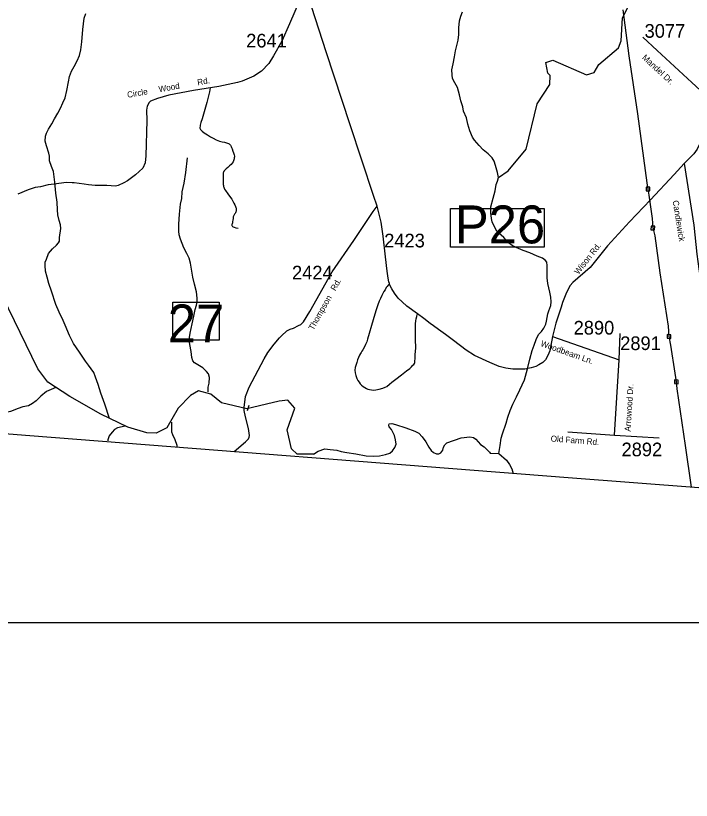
# Model space of a CAD drawing. Extents: x 1268485 to 1426702, y 514839 to 616766.
# Drawn here: x 1345954 to 1353261, y 515585 to 524068 of the extents above; entities that cross this region are included whole.
import ezdxf

# ---------------------------------------------------------------- set-up
doc = ezdxf.new("R2010")
doc.units = 0
for name, color, linetype in [('Old_Level_11', 7, 'Continuous'), ('Old_Level_31', 7, 'Continuous'), ('Old_Level_32', 7, 'Continuous'), ('Old_Level_35', 7, 'Continuous'), ('Old_Level_50', 7, 'Continuous'), ('Old_Level_52', 7, 'Continuous'), ('Old_Level_56', 7, 'Continuous'), ('Old_Level_59', 7, 'Continuous'), ('Old_Level_62', 7, 'Continuous'), ('Old_Level_63', 7, 'Continuous'), ('Old_Level_8', 7, 'Continuous')]:
    doc.layers.add(name, color=color, linetype=linetype)

msp = doc.modelspace()

# ---------------------------------------------------------------- linework, layer by layer
at = {"layer": 'Old_Level_31'}
for p, q in [((1351484.328, 520249.176), (1351484.328, 520249.176)), ((1348424.398, 519825.479), (1348424.398, 519825.479))]:
    msp.add_line(p, q, dxfattribs=at)
for points in [[(1350656.142, 521982.598), (1351670.986, 521982.598), (1351670.986, 521563.836), (1350656.142, 521563.836), (1350656.142, 521982.598)], [(1347652.648, 520970.323), (1348154.735, 520970.323), (1348154.735, 520560.496), (1347652.648, 520560.496), (1347652.648, 520970.323)]]:
    msp.add_lwpolyline(points, dxfattribs=at)
at = {"layer": 'Old_Level_32'}
for p, q in [((1352481.441, 520346.066), (1352491.89, 520631.785)), ((1351759.284, 520600.135), (1352481.441, 520346.066)), ((1352430.298, 519531.943), (1352481.441, 520346.066)), ((1351926.445, 519570.535), (1352430.298, 519531.943)), ((1352430.298, 519531.943), (1352912.367, 519503.458))]:
    msp.add_line(p, q, dxfattribs=at)
for points in [[(1349862.272, 522009.451), (1349824.73, 522122.46), (1349572.702, 522887.349), (1349310.782, 523676.541), (1349155.206, 524158.101), (1349105.065, 524367.979)], [(1349065.286, 524334.899), (1348915.363, 523981.746), (1348833.108, 523793.006), (1348743.774, 523634.247), (1348691.425, 523551.301), (1348611.448, 523469.811), (1348528.119, 523414.661), (1348405.16, 523361.807), (1348352.123, 523345.267), (1348151.34, 523301.161), (1347877.629, 523257.975), (1347608.654, 523210.193), (1347489.32, 523173.437), (1347411.931, 523143.266), (1347398.844, 523128.714), (1347376.864, 523088.761), (1347370.018, 523046.878), (1347371.363, 522934.797), (1347361.036, 522554.496), (1347355.219, 522478.827), (1347327.591, 522420.619), (1347249.068, 522346.404), (1347163.273, 522282.376), (1347125.466, 522260.548), (1347061.484, 522231.445), (1347032.401, 522225.624), (1346939.337, 522232.9), (1346812.826, 522232.9), (1346740.168, 522240.774), (1346694.707, 522248.126), (1346586.253, 522261.667), (1346564.251, 522262.11), (1346504.341, 522263.747), (1346419.102, 522252.72), (1346369.854, 522245.369), (1346305.451, 522238.018), (1346224.001, 522217.803), (1346163.387, 522210.451), (1346087.619, 522186.56), (1345975.863, 522138.779)], [(1353537.161, 523096.675), (1353266.596, 523346.181), (1352892.233, 523690.602), (1352735.016, 523837.622)], [(1353537.161, 523096.675), (1353500.054, 522977.251), (1353413.978, 522807.132), (1353324.923, 522623.315), (1353287.817, 522575.04), (1353184.651, 522468.203)], [(1353184.651, 522468.203), (1353074.457, 522349.632), (1352818.424, 522077.436), (1352593.932, 521837.917), (1352354.596, 521579.832), (1352166.735, 521344.382), (1351977.972, 521183.613), (1351951.997, 521150.191), (1351911.18, 521074.065), (1351866.653, 520966.375), (1351851.81, 520916.243), (1351796.221, 520744.399), (1351759.284, 520600.135)], [(1353184.651, 522468.203), (1353289.673, 521801.897), (1353321.213, 521489.966), (1353363.462, 521174.024)], [(1348425.689, 519823.896), (1348425.319, 519832.419), (1348438.406, 519950.871), (1348480.576, 520050.698), (1348640.531, 520356.287), (1348679.792, 520426.136), (1348748.91, 520515.931), (1348808.282, 520586.487), (1348828.691, 520606.911), (1348886.104, 520662.242), (1348922.668, 520679.514), (1348958.94, 520690.464), (1349012.746, 520718.315), (1349038.721, 520729.455), (1349047.999, 520740.596), (1349060.986, 520751.736), (1349068.408, 520759.163), (1349136.819, 520870.899), (1349376.031, 521298.729), (1349612.058, 521636.906), (1349821.106, 521952.452), (1349862.272, 522009.451)], [(1351759.284, 520600.135), (1351730.398, 520445.305), (1351710.51, 520393.847), (1351682.097, 520346.985), (1351653.684, 520316.662), (1351612.516, 520294.237), (1351580.975, 520273.813), (1351527.169, 520260.816), (1351460.952, 520245.449), (1351415.845, 520245.962), (1351330.497, 520247.819), (1351255.907, 520256.015), (1351182.034, 520274.393), (1351081.642, 520316.662), (1350915.901, 520395.685), (1350825.927, 520451.736), (1350687.179, 520556.029), (1350601.941, 520620.35), (1350526.173, 520674.564), (1350473.61, 520714.535), (1350437.62, 520740.263), (1350369.43, 520792.639), (1350298.398, 520843.177), (1350185.695, 520926.794), (1350134.553, 520972.738), (1350090.986, 521015.006), (1350049.787, 521068.761), (1350022.321, 521114.705), (1350000.538, 521154.216), (1349996.096, 521171.883), (1349991.067, 521191.89), (1349982.069, 521231.861), (1349970.704, 521304.452), (1349953.657, 521461.58), (1349927.146, 521683.791), (1349908.197, 521835.561), (1349862.272, 522009.451)], [(1348316.159, 519354.427), (1348439.86, 519461.928), (1348470.397, 519493.943), (1348479.516, 519511.362), (1348483.186, 519529.499), (1348470.397, 519604.537), (1348439.525, 519729.578), (1348426.773, 519798.949), (1348425.689, 519823.896)]]:
    msp.add_lwpolyline(points, dxfattribs=at)
at = {"layer": 'Old_Level_35'}
for points in [[(1348058.225, 523288.458), (1348050.023, 523245.192), (1348020.393, 523128.773), (1347992.096, 523026.76), (1347970.361, 522953.095), (1347957.237, 522912.956), (1347949.958, 522885.325), (1347947.395, 522872.817), (1347945.344, 522859.642), (1347946.78, 522853.08), (1347948.625, 522845.186), (1347952.624, 522837.291), (1347958.468, 522828.731), (1347969.745, 522818.888), (1347990.763, 522802.382), (1348030.236, 522778.083), (1348062.532, 522757.014), (1348089.496, 522742.557), (1348121.792, 522726.768), (1348158.496, 522712.261), (1348186.896, 522704.367), (1348212.527, 522699.138), (1348232.827, 522694.524), (1348245.951, 522690.577), (1348254.05, 522687.296), (1348261.842, 522682.682), (1348270.352, 522675.454), (1348277.016, 522668.226), (1348281.63, 522660.947), (1348284.911, 522654.385), (1348288.704, 522644.542), (1348294.138, 522630.035), (1348303.98, 522603.071), (1348311.157, 522584.001), (1348314.541, 522572.826), (1348317.104, 522562.266), (1348319.154, 522550.424), (1348319.769, 522540.581), (1348318.334, 522530.021), (1348317.104, 522520.178), (1348314.541, 522510.336), (1348311.157, 522500.443), (1348304.596, 522487.268), (1348295.983, 522472.811), (1348284.295, 522459.022), (1348267.174, 522443.181), (1348249.334, 522428.059), (1348229.034, 522411.603), (1348218.371, 522401.095), (1348211.092, 522393.2), (1348207.298, 522388.587), (1348203.3, 522382.64), (1348200.634, 522376.078), (1348198.584, 522368.184), (1348198.584, 522357.675), (1348197.968, 522330.71), (1348197.968, 522289.905), (1348198.584, 522262.275), (1348199.404, 522243.205), (1348200.019, 522231.978), (1348201.967, 522222.135), (1348204.018, 522212.96), (1348207.298, 522203.732), (1348212.527, 522193.838), (1348221.755, 522178.716), (1348248.616, 522143.19), (1348277.631, 522103.052), (1348290.755, 522083.315), (1348302.648, 522062.912), (1348314.541, 522041.228), (1348323.665, 522023.44), (1348331.662, 522006.37), (1348335.456, 521995.809), (1348337.506, 521987.248), (1348338.839, 521978.738), (1348339.454, 521966.897), (1348339.454, 521956.337), (1348336.174, 521945.828), (1348332.278, 521936.6), (1348327.664, 521928.706), (1348321.717, 521921.478), (1348315.771, 521914.865), (1348311.875, 521908.303), (1348309.209, 521901.741), (1348306.646, 521891.899), (1348304.596, 521874.111), (1348302.648, 521857.655), (1348299.982, 521841.2), (1348297.419, 521829.358), (1348294.753, 521817.517), (1348292.703, 521808.955), (1348293.42, 521801.061), (1348295.368, 521795.166), (1348299.982, 521789.219), (1348306.646, 521783.991), (1348315.771, 521780.043), (1348334.841, 521774.763), (1348360.472, 521770.15)], [(1349995.865, 521168.167), (1349983.254, 521153.558), (1349972.387, 521141.716), (1349962.339, 521128.08), (1349948.601, 521105.371), (1349936.913, 521084.455), (1349914.972, 521043.547), (1349899.593, 521010.79), (1349885.957, 520981.724), (1349872.219, 520943.533), (1349848.638, 520875.353), (1349819.623, 520778.979), (1349760.465, 520568.954), (1349751.341, 520542.554), (1349738.422, 520512.513), (1349721.916, 520481.346), (1349707.254, 520456.791), (1349698.027, 520440.899), (1349688.595, 520426.187), (1349681.418, 520414.396), (1349673.216, 520397.069), (1349662.245, 520370.72), (1349651.378, 520346.165), (1349642.253, 520318.022), (1349631.385, 520285.265), (1349625.028, 520264.35), (1349622.26, 520236.155), (1349626.874, 520207.088), (1349631.385, 520178.894), (1349644.098, 520146.137), (1349654.966, 520123.427), (1349667.782, 520104.357), (1349680.495, 520087.953), (1349694.951, 520072.523), (1349710.535, 520060.681), (1349730.528, 520047.045), (1349746.829, 520038.895), (1349764.156, 520031.615), (1349782.201, 520026.182), (1349802.296, 520022.491), (1349823.211, 520020.696), (1349847.715, 520023.413), (1349885.957, 520029.77), (1349925.02, 520041.611), (1349949.626, 520050.685), (1349967.773, 520060.681), (1349995.045, 520082.519), (1350022.419, 520105.229), (1350064.147, 520137.986), (1350126.893, 520185.25), (1350180.412, 520227.85), (1350218.244, 520255.071), (1350234.751, 520271.68), (1350250.745, 520288.238), (1350260.587, 520297.516), (1350266.636, 520306.18), (1350269.2, 520316.125), (1350270.02, 520326.736), (1350271.25, 520338.014), (1350272.583, 520357.289), (1350273.916, 520381.793), (1350275.864, 520404.4), (1350280.477, 520472.58), (1350279.657, 520570.748), (1350277.709, 520675.325), (1350277.709, 520735.303), (1350280.477, 520767.137), (1350284.168, 520791.692), (1350291.55, 520816.247), (1350296.471, 520836.393)]]:
    msp.add_lwpolyline(points, dxfattribs=at)
at = {"layer": 'Old_Level_50'}
for p, q in [((1351484.328, 520249.176), (1351484.328, 520249.176)), ((1348424.398, 519825.479), (1348424.398, 519825.479))]:
    msp.add_line(p, q, dxfattribs=at)
at = {"layer": 'Old_Level_52'}
msp.add_lwpolyline([(1390386.565, 515584.903), (1384780.066, 516073.469), (1382090.885, 516373.285), (1380837.056, 516499.357), (1377653.026, 516857.552), (1375435.218, 517115.671), (1374243.431, 517242.496), (1370986.027, 517544.143), (1365028.634, 518085.998), (1364947.704, 518099.982), (1362624.375, 518268.785), (1357811.876, 518630.949), (1356167.665, 518747.074), (1351928.686, 519072.487), (1346107.779, 519526.78), (1342010.801, 519849.137), (1339673.829, 520032.629), (1338463.06, 520121.224), (1334735.72, 520417.336), (1328377.203, 520903.463), (1327643.106, 520964.699), (1325231.308, 521115.741), (1322642.809, 521300.009)], dxfattribs=at)
at = {"layer": 'Old_Level_56'}
for points in [[(1352518.426, 524132.236), (1352583.394, 523632.491), (1352679.666, 523008.057), (1352779.24, 522259.497), (1352791.911, 522193.211), (1352800.382, 522127.009), (1352838.944, 521875.914), (1352844.69, 521773.749), (1352864.799, 521689.305), (1352921.94, 521287.765), (1353009.379, 520711.531), (1353018.923, 520599.286), (1353036.87, 520506.881), (1353082.189, 520203.825), (1353098.093, 520109.26), (1353104.362, 520033.098), (1353193.075, 519420.822), (1353259.865, 518970.296)], [(1352771.507, 522173.612), (1352811.51, 522172.807), (1352812.315, 522212.81), (1352772.312, 522213.615), (1352771.507, 522173.612)], [(1352824.285, 521754.151), (1352864.289, 521753.346), (1352865.093, 521793.348), (1352825.091, 521794.154), (1352824.285, 521754.151)], [(1352998.519, 520579.687), (1353038.521, 520578.882), (1353039.327, 520618.885), (1352999.324, 520619.69), (1352998.519, 520579.687)], [(1353077.689, 520089.661), (1353117.692, 520088.856), (1353118.497, 520128.859), (1353078.494, 520129.664), (1353077.689, 520089.661)]]:
    msp.add_lwpolyline(points, dxfattribs=at)
at = {"layer": 'Old_Level_59'}
for points in [[(1351175.94, 522318.92), (1351278.261, 522389.919), (1351475.316, 522625.627), (1351594.246, 523115.547), (1351732.246, 523322.906), (1351734.297, 523421.28), (1351710.306, 523447.988), (1351687.237, 523563.381), (1351763.312, 523588.141), (1352126.254, 523429.841), (1352210.223, 523454.396), (1352262.306, 523541.953), (1352474.227, 523721.476), (1352501.294, 523796.474), (1352515.238, 524045.663), (1352698.247, 524399.737)], [(1351180.246, 519335.054), (1351194.087, 519422.611), (1351205.775, 519498.685), (1351216.95, 519548.513), (1351257.346, 519661.752), (1351274.98, 519728.702), (1351302.354, 519798.727), (1351330.037, 519867.932), (1351369.817, 519946.724), (1351405.393, 520022.336), (1351455.836, 520129.63), (1351488.542, 520250.406), (1351514.788, 520355.751), (1351540.83, 520449.614), (1351560.207, 520507.49), (1351583.583, 520568.544), (1351606.652, 520620.628), (1351639.46, 520655.23), (1351666.219, 520689.166), (1351687.135, 520732.227), (1351695.952, 520764.061), (1351709.69, 520845.826), (1351718.405, 520877.66), (1351739.731, 520935.485), (1351746.497, 520973.112), (1351741.679, 521025.708), (1351730.913, 521080.098), (1351708.87, 521174.114), (1351702.206, 521234.143), (1351703.129, 521368.708), (1351698.002, 521402.439), (1351682.419, 521420.843), (1351650.84, 521446.065), (1351595.374, 521469.338), (1351514.071, 521502.967), (1351442.61, 521528.239), (1351367.356, 521561.765), (1351321.732, 521584.833), (1351284.412, 521613.49), (1351233.56, 521668.649), (1351178.503, 521716.528), (1351157.075, 521739.135), (1351124.472, 521799.677), (1351107.247, 521837.765), (1351098.02, 521874.059), (1351091.458, 521938.19), (1351092.791, 522000.576), (1351118.935, 522096.028), (1351138.62, 522175.23), (1351150.103, 522241.462), (1351163.022, 522278.986), (1351175.94, 522318.92)], [(1349174.709, 519325.848), (1348997.812, 519325.848), (1348935.898, 519383.38), (1348891.674, 519591.38), (1348971.277, 519825.933), (1348896.096, 519910.019), (1348803.225, 519901.168), (1348453.361, 519817.489), (1348179.411, 519882.132), (1348065.402, 519976.302), (1347932.004, 520011.806), (1347843.556, 519963.125), (1347710.883, 519825.933), (1347590.399, 519611.669), (1347472.392, 519554.972), (1347372.429, 519556.971), (1347165.429, 519620.229), (1346875.042, 519759.551), (1346538.379, 519951.183), (1346300.416, 520107.023), (1346195.43, 520250.252), (1345748.416, 521161.965)], [(1349174.709, 519325.848), (1349226.444, 519361.35), (1349297.203, 519383.478), (1349354.694, 519379.052), (1349425.454, 519370.201), (1349473.803, 519354.636), (1349533.678, 519346.844), (1349631.283, 519330.952), (1349744.881, 519308.14), (1349828.85, 519306.449), (1349888.93, 519309.37), (1349953.317, 519323.673), (1349999.659, 519339.155), (1350028.263, 519362.376), (1350055.023, 519397.902), (1350067.736, 519433.786), (1350062.917, 519483.921), (1350049.896, 519530.161), (1350017.293, 519592.342), (1349993.917, 519623.203), (1349990.329, 519639.658), (1349994.635, 519655.191), (1350022.727, 519658.728), (1350062.507, 519648.066), (1350171.8, 519611.412), (1350271.045, 519577.373), (1350312.568, 519554.408), (1350349.785, 519515.089), (1350388.54, 519460.135), (1350423.296, 519402.003), (1350446.57, 519368.733), (1350472.099, 519346.844), (1350505.727, 519331.413), (1350531.769, 519330.901), (1350552.069, 519342.794), (1350572.677, 519371.911), (1350581.213, 519401.212), (1350594.479, 519427.766), (1350616.591, 519449.893), (1350771.377, 519502.999), (1350864.248, 519516.276), (1350904.05, 519507.425), (1350930.584, 519489.723), (1350979.232, 519432.191), (1351019.033, 519405.638), (1351076.525, 519348.106), (1351085.37, 519339.255), (1351180.246, 519335.054)], [(1351180.246, 519335.054), (1351260.626, 519262.875), (1351295.588, 519216.226), (1351318.554, 519168.192), (1351334.113, 519118.891)]]:
    msp.add_lwpolyline(points, dxfattribs=at)
at = {"layer": 'Old_Level_62'}
msp.add_line((1348460.743, 519800.368), (1348479.71, 519858.705), dxfattribs=at)
for points in [[(1346969.835, 519714.071), (1346917.726, 519867.266), (1346876.408, 519987.888), (1346846.47, 520078.777), (1346818.173, 520158.953), (1346799.206, 520209.396), (1346770.191, 520250.149), (1346743.021, 520289.263), (1346709.905, 520333.452), (1346644.084, 520429.16), (1346578.16, 520523.176), (1346537.867, 520609.35), (1346490.397, 520722.744), (1346467.431, 520771.597), (1346425.498, 520864.383), (1346389.307, 520945.533), (1346342.452, 521088.402), (1346314.258, 521171.038), (1346293.65, 521241.218), (1346277.143, 521305.552), (1346272.529, 521367.991), (1346273.247, 521401.671), (1346288.011, 521435.812), (1346307.286, 521495.328), (1346350.552, 521548.642), (1346395.356, 521587.089), (1346415.963, 521612.977), (1346426.318, 521630.817), (1346429.189, 521668.495), (1346441.39, 521766.715), (1346438.211, 521806.187), (1346423.243, 521854.887), (1346410.632, 521915.07), (1346407.864, 521969.255), (1346401.61, 522051.429), (1346387.769, 522150.214), (1346376.286, 522267.811), (1346362.855, 522382.127), (1346342.042, 522436.722), (1346319.384, 522497.879), (1346320.512, 522549.553), (1346311.284, 522583.386), (1346288.934, 522662.639), (1346274.067, 522710.518), (1346277.246, 522764.6), (1346288.011, 522798.024), (1346308.824, 522840.316), (1346346.246, 522899.422), (1346375.466, 522952.223), (1346408.787, 523015.533), (1346438.006, 523067.462), (1346463.228, 523126.877), (1346490.5, 523180.498), (1346508.339, 523259.699), (1346526.281, 523351.254), (1346537.559, 523409.284), (1346556.937, 523468.801), (1346588.002, 523518.269), (1346617.324, 523579.222), (1346644.596, 523636.944), (1346660.078, 523698.972), (1346669.92, 523786.58), (1346680.891, 523918.48), (1346693.604, 524040.486), (1346712.674, 524091.8)], [(1351175.94, 522318.92), (1351163.022, 522370.9), (1351142.721, 522447.59), (1351127.753, 522495.521), (1351106.53, 522530.38), (1351063.469, 522575.594), (1351010.463, 522618.501), (1350965.351, 522663.715), (1350916.549, 522720.514), (1350895.326, 522752.913), (1350866.824, 522821.605), (1350842.423, 522895.936), (1350827.864, 522964.373), (1350795.466, 523037.217), (1350788.494, 523081.663), (1350769.834, 523146.049), (1350753.328, 523212.024), (1350731.079, 523292.917), (1350702.065, 523341.925), (1350679.099, 523388.318), (1350673.972, 523428.662), (1350671.204, 523482.027), (1350684.635, 523548.259), (1350698.374, 523623.461), (1350711.702, 523687.181), (1350725.03, 523745.211), (1350738.359, 523804.83), (1350745.638, 523864.602), (1350745.228, 523935.192), (1350754.865, 524012.958), (1350767.989, 524062.734), (1350785.008, 524108.358)], [(1348035.354, 520001.122), (1348036.387, 520050.736), (1348045.307, 520094.054), (1348048.691, 520156.338), (1348039.566, 520194.273), (1348018.138, 520222.621), (1347979.075, 520261.94), (1347941.346, 520282.394), (1347888.135, 520315.458), (1347868.655, 520338.014), (1347859.427, 520372.668), (1347850.713, 520436.849), (1347838.41, 520513.436), (1347831.643, 520566.904), (1347841.178, 520637.288), (1347861.375, 520736.995), (1347879.215, 520820.348), (1347894.799, 520889.758), (1347909.87, 520939.534), (1347916.637, 520975.521), (1347917.56, 521013.251), (1347909.05, 521083.994), (1347886.802, 521164.016), (1347870.5, 521240.653), (1347845.792, 521391.316), (1347830.925, 521445.808), (1347806.216, 521497.994), (1347773.408, 521559.356), (1347737.421, 521652.04), (1347720.505, 521699.97), (1347717.326, 521738.572), (1347717.019, 521812.441), (1347727.374, 521920.555), (1347737.832, 522031.949), (1347751.16, 522091.569), (1347754.748, 522163.747), (1347774.843, 522257.712), (1347793.401, 522371.413), (1347812.778, 522530.995)], [(1346388.918, 520049.065), (1346286.575, 520004.702), (1346227.418, 519955.797), (1346174.207, 519903.56), (1346135.555, 519873.981), (1346091.058, 519851.067), (1346030.773, 519838.302), (1345982.278, 519819.592), (1345899.54, 519787.603), (1345790.965, 519763.561), (1345720.529, 519743.62), (1345665.78, 519716.809), (1345629.281, 519691.332), (1345586.528, 519654.422), (1345515.17, 519597.571), (1345484.874, 519587.704), (1345461.036, 519589.626)], [(1347138.001, 519628.611), (1347054.29, 519611.771), (1347021.79, 519592.701), (1346997.081, 519565.327), (1346964.375, 519525.752), (1346951.354, 519481.717), (1346949.201, 519469.67)], [(1347640.323, 519673.784), (1347639.612, 519568.813), (1347648.942, 519539.08), (1347673.753, 519486.023), (1347698.462, 519423.174), (1347698.154, 519409.333)]]:
    msp.add_lwpolyline(points, dxfattribs=at)
at = {"layer": 'Old_Level_63'}
msp.add_lwpolyline([(1305516.95, 529802.059), (1368033.021, 529802.059), (1368033.021, 517504.204), (1305516.95, 517504.204), (1305516.95, 529802.059)], dxfattribs=at)

# ---------------------------------------------------------------- texts
at = {"layer": 'Old_Level_11'}
for s, height, rotation, p in [('Mandel Dr.', 65.6167, 317.3853389, (1352722.862, 523607.224)), ('Circle     Wood        Rd.', 65.61666, 10.0732222, (1347165.369, 523179.588)), ('Candlewick', 65.6167, 278.9571528, (1353058.578, 522066.401)), ('Wison Rd.', 65.6167, 51.4142389, (1352039.354, 521264.518)), ('Thompson   Rd.', 65.61666, 60.7892111, (1349173.637, 520661.037)), ('Woodbeam Ln.', 65.61666, 340.6171472, (1351624.746, 520497.184)), ('Arrowood Dr.', 65.61666, 86.4054, (1352603.608, 519570.228)), ('Old Farm Rd.', 65.61666, 355.6199972, (1351737.947, 519464.575))]:
    msp.add_text(s, height=height, rotation=rotation, dxfattribs=at).set_placement(p)
at = {"layer": 'Old_Level_31'}
for s, p in [('P26', (1350703.898, 521606.11)), ('27', (1347599.039, 520535.332))]:
    msp.add_text(s, height=410.1042, dxfattribs=at).set_placement(p)
at = {"layer": 'Old_Level_8'}
for s, p in [('3077', (1352755.304, 523829.419)), ('2641', (1348446.869, 523724.359)), ('2423', (1349939.585, 521562.874)), ('2424', (1348942.545, 521216.369)), ('2890', (1351988.136, 520620.361)), ('2891', (1352491.92, 520452.944)), ('2892', (1352505.982, 519304.3))]:
    msp.add_text(s, height=147.6375, dxfattribs=at).set_placement(p)

doc.saveas('drawing.dxf')
